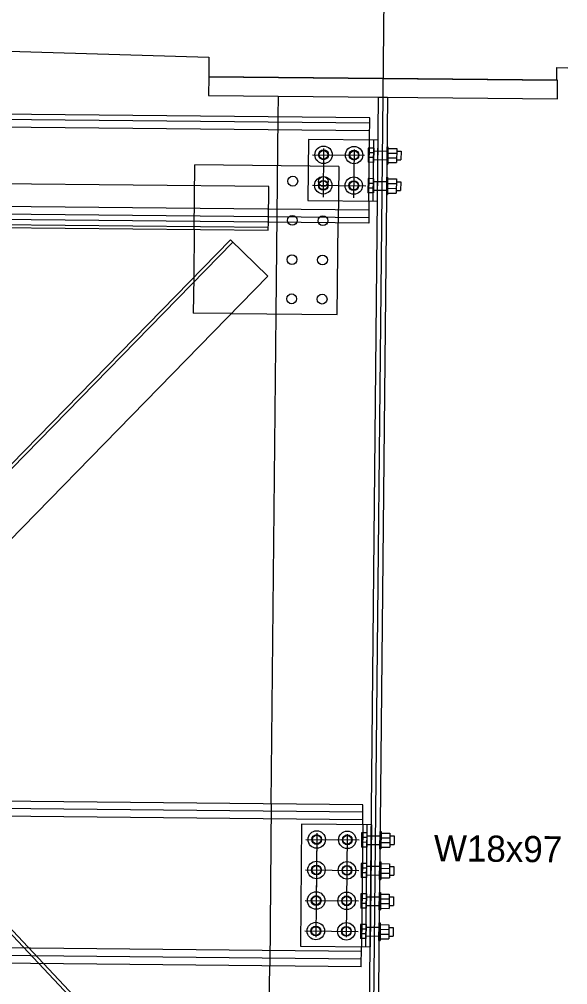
# Model space of a CAD drawing. Extents: x 632312 to 632885, y 378199 to 378534.
# Drawn here: x 632401.08 to 632406.32, y 378386.51 to 378395.75 of the extents above; entities that cross this region are included whole.
import ezdxf

# ---------------------------------------------------------------- set-up
doc = ezdxf.new("R2010")
doc.units = 0
for name, color, linetype in [('B_Boring', 7, 'Continuous'), ('B_Boring Annot', 7, 'Continuous'), ('R_Proposed Const Limits Cut', 7, 'Continuous'), ('R_Shade Removal', 7, 'Continuous'), ('R_Wall', 7, 'Continuous'), ('SHT_Dimensions', 7, 'Continuous')]:
    doc.layers.add(name, color=color, linetype=linetype)

msp = doc.modelspace()

# ---------------------------------------------------------------- linework, layer by layer
at = {"layer": 'B_Boring'}
for p, q in [((632403.5556, 378394.8124), (632403.5576, 378395.0114)), ((632404.4301, 378394.7533), (632393.4306, 378394.8626)), ((632404.4306, 378394.8037), (632393.4311, 378394.913)), ((632404.4284, 378394.5912), (632404.4306, 378394.8037)), ((632403.8451, 378394.597), (632403.8393, 378394.0137)), ((632404.5118, 378394.5904), (632403.8451, 378394.597)), ((632404.4643, 378394.0075), (632404.4701, 378394.5908)), ((632404.506, 378394.0071), (632404.5118, 378394.5904)), ((632404.4173, 378394.5132), (632404.4159, 378394.3778)), ((632404.4693, 378394.5127), (632404.4173, 378394.5132)), ((632404.4693, 378394.5127), (632404.468, 378394.3773)), ((632404.5945, 378394.5271), (632404.5928, 378394.3604)), ((632404.5945, 378394.5271), (632404.6049, 378394.527)), ((632404.6049, 378394.527), (632404.6032, 378394.3603)), ((632404.6047, 378394.5113), (632404.6881, 378394.5105)), ((632404.6881, 378394.5105), (632404.6867, 378394.3751)), ((632404.4684, 378394.4224), (632404.4164, 378394.4229)), ((632404.4689, 378394.4675), (632404.4168, 378394.4681)), ((632404.6038, 378394.4211), (632404.6872, 378394.4202)), ((632404.6043, 378394.4662), (632404.6876, 378394.4654)), ((632404.687, 378394.4011), (632404.7287, 378394.4007)), ((632404.6878, 378394.4845), (632404.7295, 378394.484)), ((632404.7295, 378394.484), (632404.7287, 378394.4007)), ((632402.7593, 378394.3526), (632402.7593, 378394.3526)), ((632404.468, 378394.3773), (632404.4159, 378394.3778)), ((632404.5928, 378394.3604), (632404.6032, 378394.3603)), ((632404.6034, 378394.3759), (632404.6867, 378394.3751)), ((632404.4144, 378394.2215), (632404.413, 378394.0861)), ((632404.4664, 378394.221), (632404.4144, 378394.2215)), ((632404.4664, 378394.221), (632404.4651, 378394.0856)), ((632404.5916, 378394.2354), (632404.5899, 378394.0687)), ((632404.5916, 378394.2354), (632404.602, 378394.2353)), ((632404.602, 378394.2353), (632404.6003, 378394.0686)), ((632404.6018, 378394.2197), (632404.6852, 378394.2188)), ((632404.6852, 378394.2188), (632404.6838, 378394.0834)), ((632404.4655, 378394.1308), (632404.4135, 378394.1313)), ((632404.466, 378394.1759), (632404.4139, 378394.1764)), ((632404.601, 378394.1294), (632404.6843, 378394.1286)), ((632404.6014, 378394.1745), (632404.6847, 378394.1737)), ((632404.6849, 378394.1928), (632404.7266, 378394.1924)), ((632404.7266, 378394.1924), (632404.7258, 378394.1091)), ((632404.4651, 378394.0856), (632404.413, 378394.0861)), ((632404.5899, 378394.0687), (632404.6003, 378394.0686)), ((632404.6005, 378394.0843), (632404.6838, 378394.0834)), ((632404.6841, 378394.1095), (632404.7258, 378394.1091)), ((632404.421, 378393.8458), (632393.4216, 378393.9552)), ((632403.8393, 378394.0137), (632404.506, 378394.0071)), ((632404.4226, 378394.0079), (632404.4205, 378393.7954)), ((632404.4205, 378393.7954), (632393.4211, 378393.9048)), ((632398.9201, 378393.7741), (632403.4615, 378393.7289)), ((632403.4615, 378393.7289), (632403.4623, 378393.8049)), ((632404.1202, 378392.9223), (632404.1289, 378393.7983)), ((632403.11, 378392.9324), (632404.1202, 378392.9223)), ((632403.4903, 378388.2445), (632403.5369, 378392.9281)), ((632404.3653, 378388.2359), (632393.3658, 378388.3452)), ((632404.3645, 378388.1634), (632393.3651, 378388.2727)), ((632404.3634, 378388.0442), (632404.3653, 378388.2359)), ((632403.7801, 378388.05), (632403.7685, 378386.8834)), ((632404.4467, 378388.0434), (632403.7801, 378388.05)), ((632404.3934, 378386.8772), (632404.405, 378388.0438)), ((632404.4467, 378388.0434), (632404.4351, 378386.8768)), ((632404.3522, 378387.9662), (632404.3508, 378387.8308)), ((632404.4042, 378387.9656), (632404.3522, 378387.9662)), ((632404.4456, 378387.9392), (632404.529, 378387.9384)), ((632404.5277, 378387.8134), (632404.5294, 378387.98)), ((632404.5294, 378387.98), (632404.5398, 378387.9799)), ((632404.5398, 378387.9799), (632404.5382, 378387.8133)), ((632404.5397, 378387.9643), (632404.623, 378387.9635)), ((632404.623, 378387.9635), (632404.6216, 378387.8281)), ((632404.4033, 378387.8754), (632404.3513, 378387.8759)), ((632404.4038, 378387.9205), (632404.3517, 378387.921)), ((632404.4448, 378387.8559), (632404.5282, 378387.855)), ((632404.5388, 378387.874), (632404.6221, 378387.8732)), ((632404.5392, 378387.9192), (632404.6225, 378387.9183)), ((632404.6219, 378387.8541), (632404.6636, 378387.8537)), ((632404.6227, 378387.9374), (632404.6644, 378387.937)), ((632404.6644, 378387.937), (632404.6636, 378387.8537)), ((632404.4029, 378387.8303), (632404.3508, 378387.8308)), ((632404.5277, 378387.8134), (632404.5382, 378387.8133)), ((632404.5383, 378387.8289), (632404.6216, 378387.8281)), ((632404.3493, 378387.6745), (632404.3479, 378387.5391)), ((632404.4013, 378387.674), (632404.3493, 378387.6745)), ((632404.5248, 378387.5217), (632404.5265, 378387.6884)), ((632404.5265, 378387.6884), (632404.5369, 378387.6883)), ((632404.5369, 378387.6883), (632404.5353, 378387.5216)), ((632404.5368, 378387.6727), (632404.6201, 378387.6718)), ((632404.6201, 378387.6718), (632404.6187, 378387.5364)), ((632404.4004, 378387.5837), (632404.3484, 378387.5842)), ((632404.4009, 378387.6289), (632404.3488, 378387.6294)), ((632404.5359, 378387.5824), (632404.6192, 378387.5816)), ((632404.5363, 378387.6275), (632404.6196, 378387.6267)), ((632404.6198, 378387.6458), (632404.6615, 378387.6454)), ((632404.6615, 378387.6454), (632404.6607, 378387.562)), ((632404.4, 378387.5386), (632404.3479, 378387.5391)), ((632404.5248, 378387.5217), (632404.5353, 378387.5216)), ((632404.5354, 378387.5373), (632404.6187, 378387.5364)), ((632404.619, 378387.5625), (632404.6607, 378387.562)), ((632404.5219, 378387.2301), (632404.5236, 378387.3967)), ((632404.5236, 378387.3967), (632404.534, 378387.3966)), ((632404.534, 378387.3966), (632404.5324, 378387.23)), ((632404.3464, 378387.3829), (632404.345, 378387.2475)), ((632404.398, 378387.3372), (632404.3459, 378387.3377)), ((632404.3984, 378387.3823), (632404.3464, 378387.3829)), ((632404.5334, 378387.3359), (632404.6167, 378387.335)), ((632404.5339, 378387.381), (632404.6172, 378387.3802)), ((632404.6172, 378387.3802), (632404.6158, 378387.2448)), ((632404.6169, 378387.3541), (632404.6586, 378387.3537)), ((632404.6586, 378387.3537), (632404.6578, 378387.2704)), ((632404.3971, 378387.247), (632404.345, 378387.2475)), ((632404.3975, 378387.2921), (632404.3455, 378387.2926)), ((632404.5219, 378387.2301), (632404.5324, 378387.23)), ((632404.5325, 378387.2456), (632404.6158, 378387.2448)), ((632404.533, 378387.2907), (632404.6163, 378387.2899)), ((632404.6161, 378387.2708), (632404.6578, 378387.2704)), ((632404.3435, 378387.0912), (632404.3421, 378386.9558)), ((632404.3951, 378387.0456), (632404.343, 378387.0461)), ((632404.3955, 378387.0907), (632404.3435, 378387.0912)), ((632404.519, 378386.9384), (632404.5207, 378387.1051)), ((632404.5207, 378387.1051), (632404.5311, 378387.105)), ((632404.5311, 378387.105), (632404.5295, 378386.9383)), ((632404.5305, 378387.0442), (632404.6138, 378387.0434)), ((632404.531, 378387.0893), (632404.6143, 378387.0885)), ((632404.6143, 378387.0885), (632404.6129, 378386.9531)), ((632404.614, 378387.0625), (632404.6557, 378387.0621)), ((632404.6557, 378387.0621), (632404.6549, 378386.9787)), ((632404.3942, 378386.9553), (632404.3421, 378386.9558)), ((632404.3946, 378387.0004), (632404.3426, 378387.0009)), ((632404.519, 378386.9384), (632404.5295, 378386.9383)), ((632404.5296, 378386.954), (632404.6129, 378386.9531)), ((632404.5301, 378386.9991), (632404.6134, 378386.9983)), ((632404.6132, 378386.9792), (632404.6549, 378386.9787)), ((632404.3506, 378386.7584), (632393.3511, 378386.8678)), ((632403.7685, 378386.8834), (632404.4351, 378386.8768)), ((632404.3499, 378386.6859), (632404.3518, 378386.8776)), ((632404.3499, 378386.6859), (632393.3504, 378386.7953)), ((632403.4569, 378384.8869), (632403.4749, 378386.6946))]:
    msp.add_line(p, q, dxfattribs=at)
for points in [[(632406.2241, 378394.9848), (632406.2259, 378395.1619), (632402.8927, 378395.1951), (632402.8909, 378395.018)], [(632404.4799, 378383.0016), (632404.3966, 378383.0024), (632404.5159, 378395.0018), (632404.5992, 378395.001)]]:
    msp.add_lwpolyline(points, close=True, dxfattribs=at)
for points in [[(632402.7532, 378393.736), (632402.7486, 378393.278)], [(632399.6797, 378389.4202), (632403.4571, 378393.2877), (632403.0994, 378393.6371), (632399.6849, 378390.1411)], [(632401.3126, 378386.7161), (632403.37, 378384.5241)]]:
    msp.add_lwpolyline(points, dxfattribs=at)
for centre in [(632403.9895, 378394.4497), (632404.2812, 378394.4468), (632403.6953, 378394.1974), (632403.987, 378394.1945), (632403.9866, 378394.1581), (632404.2783, 378394.1552), (632403.6916, 378393.8225), (632403.9833, 378393.8196), (632403.6879, 378393.4475), (632403.9795, 378393.4446), (632403.6841, 378393.0725), (632403.9758, 378393.0696), (632403.9244, 378387.9027), (632404.2161, 378387.8998), (632403.9215, 378387.6111), (632404.2132, 378387.6082), (632403.9186, 378387.3194), (632404.2103, 378387.3165), (632403.9157, 378387.0278), (632404.2074, 378387.0249)]:
    msp.add_circle(centre, 0.0469, dxfattribs=at)
at = {"layer": 'B_Boring Annot'}
for p, q in [((632398.9443, 378395.5024), (632402.8939, 378395.3841)), ((632402.8939, 378395.3841), (632402.8921, 378395.1949)), ((632406.2187, 378395.1618), (632406.22, 378395.2845)), ((632406.22, 378395.2845), (632406.322, 378395.2814)), ((632402.8921, 378395.1949), (632406.2187, 378395.1618))]:
    msp.add_line(p, q, dxfattribs=at)
at = {"layer": 'R_Proposed Const Limits Cut'}
for p, q in [((632404.4293, 378394.6787), (632393.4299, 378394.7881)), ((632403.5369, 378392.9281), (632403.5556, 378394.8124)), ((632404.4226, 378394.0079), (632404.4284, 378394.5912)), ((632404.4682, 378394.4033), (632404.5932, 378394.4021)), ((632404.4691, 378394.4866), (632404.5941, 378394.4854)), ((632402.7532, 378393.736), (632402.7593, 378394.3526)), ((632404.1343, 378394.3389), (632402.7593, 378394.3526)), ((632404.1343, 378394.3389), (632404.1289, 378393.7983)), ((632403.4656, 378394.1456), (632394.3828, 378394.2359)), ((632403.4623, 378393.8049), (632403.4656, 378394.1456)), ((632404.4662, 378394.195), (632404.5912, 378394.1937)), ((632404.4653, 378394.1117), (632404.5903, 378394.1104)), ((632404.4218, 378393.9204), (632393.4223, 378394.0298)), ((632403.4618, 378393.755), (632394.3789, 378393.8453)), ((632394.716, 378393.6988), (632403.3472, 378384.5027)), ((632403.1218, 378393.6153), (632394.3094, 378384.5926)), ((632402.7486, 378393.278), (632402.7452, 378392.936)), ((632403.11, 378392.9324), (632402.7452, 378392.936)), ((632399.8441, 378388.2808), (632401.3126, 378386.7161)), ((632403.4903, 378388.2445), (632403.4749, 378386.6946)), ((632404.3638, 378388.09), (632393.3644, 378388.1994)), ((632404.3634, 378388.0442), (632404.3518, 378386.8776)), ((632404.404, 378387.9396), (632404.4456, 378387.9392)), ((632404.4032, 378387.8563), (632404.4448, 378387.8559)), ((632404.4011, 378387.648), (632404.5261, 378387.6467)), ((632404.4003, 378387.5646), (632404.5253, 378387.5634)), ((632404.3982, 378387.3563), (632404.5232, 378387.3551)), ((632404.3974, 378387.273), (632404.5224, 378387.2717)), ((632404.3953, 378387.0647), (632404.5203, 378387.0634)), ((632404.3513, 378386.8318), (632393.3518, 378386.9411)), ((632404.3945, 378386.9813), (632404.5195, 378386.9801))]:
    msp.add_line(p, q, dxfattribs=at)
for centre, radius in [((632403.9895, 378394.4497), 0.0833), ((632404.2812, 378394.4468), 0.0833), ((632403.9895, 378394.4497), 0.0417), ((632404.2812, 378394.4468), 0.0417), ((632403.9866, 378394.1581), 0.0833), ((632404.2783, 378394.1552), 0.0833), ((632403.9866, 378394.1581), 0.0417), ((632404.2783, 378394.1552), 0.0417), ((632403.9244, 378387.9027), 0.0833), ((632403.9244, 378387.9027), 0.0417), ((632404.2161, 378387.8998), 0.0833), ((632404.2161, 378387.8998), 0.0417), ((632403.9215, 378387.6111), 0.0833), ((632404.2132, 378387.6082), 0.0833), ((632403.9215, 378387.6111), 0.0417), ((632404.2132, 378387.6082), 0.0417), ((632403.9186, 378387.3194), 0.0833), ((632404.2103, 378387.3165), 0.0833), ((632403.9186, 378387.3194), 0.0417), ((632404.2103, 378387.3165), 0.0417), ((632403.9157, 378387.0278), 0.0833), ((632404.2074, 378387.0249), 0.0833), ((632403.9157, 378387.0278), 0.0417), ((632404.2074, 378387.0249), 0.0417)]:
    msp.add_circle(centre, radius, dxfattribs=at)
at = {"layer": 'R_Shade Removal'}
msp.add_line((632404.4265, 378381.825), (632404.5763, 378396.89), dxfattribs=at)
at = {"layer": 'R_Wall'}
for p, q in [((632403.9901, 378394.5102), (632403.9855, 378394.0453)), ((632404.2817, 378394.501), (632404.2771, 378394.038)), ((632403.8854, 378394.4508), (632404.3799, 378394.4459)), ((632403.8825, 378394.1591), (632404.3923, 378394.154)), ((632403.925, 378387.9632), (632403.9152, 378386.9699)), ((632404.2166, 378387.954), (632404.2068, 378386.9687)), ((632403.8203, 378387.9038), (632404.3301, 378387.8987)), ((632403.8174, 378387.6121), (632404.3272, 378387.607)), ((632403.8145, 378387.3204), (632404.3243, 378387.3154)), ((632403.8116, 378387.0288), (632404.3214, 378387.0237))]:
    msp.add_line(p, q, dxfattribs=at)
at = {"layer": 'SHT_Dimensions'}
for p, q in [((632403.925, 378387.9632), (632403.9182, 378387.2731)), ((632404.4042, 378387.9656), (632404.4029, 378387.8303)), ((632404.4013, 378387.674), (632404.4, 378387.5386)), ((632404.3984, 378387.3823), (632404.3971, 378387.247)), ((632404.3955, 378387.0907), (632404.3942, 378386.9553))]:
    msp.add_line(p, q, dxfattribs=at)

# ---------------------------------------------------------------- texts
msp.add_text('W18x97', height=0.25, rotation=359.43036, dxfattribs=at).set_placement((632405.0426, 378387.6958))

doc.saveas('drawing.dxf')
